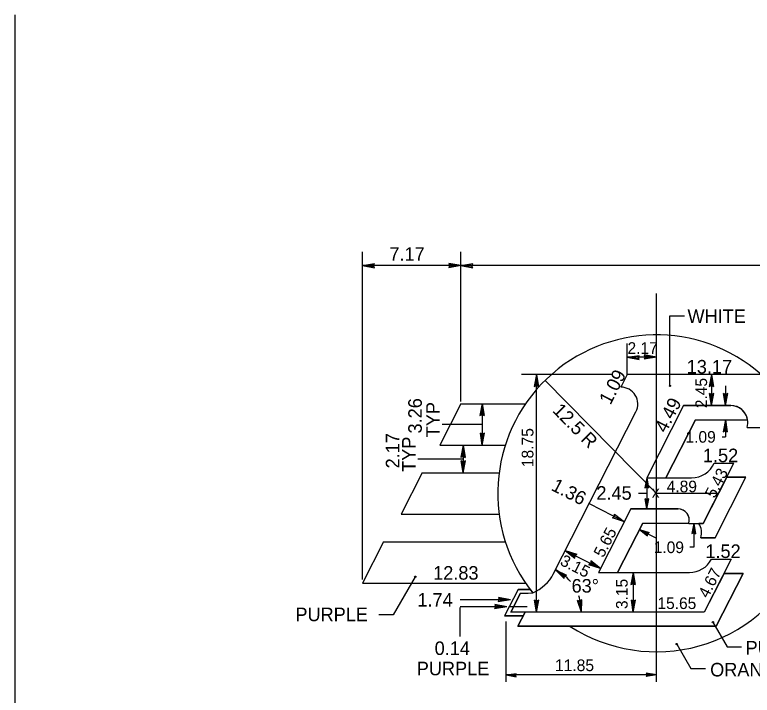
# Model space of a CAD drawing. Extents: x 10268197 to 10268826, y 2141503 to 2142677.
# Drawn here: x 10268664.32 to 10268696.97, y 2142401.45 to 2142431.59 of the extents above; entities that cross this region are included whole.
import ezdxf

# ---------------------------------------------------------------- set-up
doc = ezdxf.new("R2010")
doc.units = 0
for name, color, linetype in [('Default', 7, 'Continuous'), ('NonPlottingEle_dp', 7, 'Continuous'), ('TextMisc', 7, 'Continuous')]:
    doc.layers.add(name, color=color, linetype=linetype)

msp = doc.modelspace()

# ---------------------------------------------------------------- linework, layer by layer
at = {"layer": 'Default'}
for p, q in [((10268679.71, 2142406.582), (10268679.71, 2142421.09)), ((10268684.065, 2142415.347), (10268684.064, 2142421.09)), ((10268679.71, 2142420.48), (10268680.243, 2142420.574)), ((10268679.71, 2142420.48), (10268680.221, 2142420.524)), ((10268684.064, 2142420.48), (10268679.71, 2142420.48)), ((10268679.71, 2142420.48), (10268680.243, 2142420.386)), ((10268679.71, 2142420.48), (10268680.222, 2142420.435)), ((10268680.202, 2142420.48), (10268680.243, 2142420.574)), ((10268680.243, 2142420.386), (10268680.202, 2142420.48)), ((10268684.064, 2142420.48), (10268683.531, 2142420.574)), ((10268683.531, 2142420.574), (10268683.572, 2142420.48)), ((10268684.064, 2142420.48), (10268683.531, 2142420.386)), ((10268683.572, 2142420.48), (10268683.531, 2142420.386)), ((10268684.064, 2142420.48), (10268683.553, 2142420.524)), ((10268684.064, 2142420.48), (10268683.553, 2142420.435)), ((10268684.064, 2142420.48), (10268684.599, 2142420.565)), ((10268684.064, 2142420.48), (10268684.576, 2142420.516)), ((10268724.378, 2142420.48), (10268684.064, 2142420.48)), ((10268684.064, 2142420.48), (10268684.595, 2142420.377)), ((10268684.064, 2142420.48), (10268684.575, 2142420.426)), ((10268684.556, 2142420.471), (10268684.599, 2142420.565)), ((10268684.595, 2142420.377), (10268684.556, 2142420.471)), ((10268692.721, 2142410.391), (10268692.721, 2142419.238)), ((10268693.322, 2142418.257), (10268693.965, 2142418.258)), ((10268693.322, 2142415.153), (10268693.322, 2142418.257)), ((10268691.433, 2142415.653), (10268691.433, 2142417.027)), ((10268692.721, 2142416.417), (10268692.189, 2142416.52)), ((10268692.189, 2142416.52), (10268692.228, 2142416.425)), ((10268691.433, 2142416.417), (10268691.967, 2142416.501)), ((10268691.433, 2142416.417), (10268691.945, 2142416.453)), ((10268692.721, 2142416.417), (10268691.433, 2142416.417)), ((10268691.433, 2142416.417), (10268691.964, 2142416.314)), ((10268691.433, 2142416.417), (10268691.943, 2142416.363)), ((10268691.925, 2142416.408), (10268691.967, 2142416.501)), ((10268691.964, 2142416.314), (10268691.925, 2142416.408)), ((10268692.228, 2142416.425), (10268692.186, 2142416.332)), ((10268692.721, 2142416.417), (10268692.186, 2142416.332)), ((10268692.721, 2142416.417), (10268692.209, 2142416.381)), ((10268692.721, 2142416.417), (10268692.21, 2142416.47)), ((10268690.715, 2142415.653), (10268686.746, 2142415.654)), ((10268687.415, 2142415.653), (10268687.312, 2142415.122)), ((10268687.415, 2142415.653), (10268687.361, 2142415.142)), ((10268687.415, 2142405.129), (10268687.415, 2142415.653)), ((10268687.415, 2142415.653), (10268687.5, 2142415.119)), ((10268687.415, 2142415.653), (10268687.451, 2142415.141)), ((10268691.433, 2142415.653), (10268691.148, 2142415.096)), ((10268698.825, 2142415.653), (10268691.433, 2142415.653)), ((10268695.162, 2142415.653), (10268695.059, 2142415.122)), ((10268695.162, 2142415.653), (10268695.108, 2142415.142)), ((10268695.162, 2142415.653), (10268695.162, 2142414.275)), ((10268695.162, 2142415.653), (10268695.247, 2142415.119)), ((10268695.162, 2142415.653), (10268695.198, 2142415.141)), ((10268684.065, 2142414.457), (10268684.065, 2142415.347)), ((10268692.721, 2142410.391), (10268687.797, 2142415.39)), ((10268687.312, 2142415.122), (10268687.406, 2142415.161)), ((10268687.406, 2142415.161), (10268687.5, 2142415.119)), ((10268695.059, 2142415.122), (10268695.153, 2142415.161)), ((10268695.153, 2142415.161), (10268695.247, 2142415.119)), ((10268695.778, 2142415.155), (10268695.778, 2142414.275)), ((10268695.162, 2142414.275), (10268695.077, 2142414.81)), ((10268695.17, 2142414.768), (10268695.077, 2142414.81)), ((10268695.162, 2142414.275), (10268695.126, 2142414.787)), ((10268695.162, 2142414.275), (10268695.265, 2142414.807)), ((10268695.162, 2142414.275), (10268695.215, 2142414.786)), ((10268695.265, 2142414.807), (10268695.17, 2142414.768)), ((10268695.778, 2142414.275), (10268695.693, 2142414.81)), ((10268695.787, 2142414.767), (10268695.693, 2142414.81)), ((10268695.778, 2142414.275), (10268695.742, 2142414.787)), ((10268695.778, 2142414.275), (10268695.881, 2142414.807)), ((10268695.778, 2142414.275), (10268695.832, 2142414.786)), ((10268695.881, 2142414.807), (10268695.787, 2142414.767)), ((10268684.064, 2142414.351), (10268683.132, 2142412.521)), ((10268684.064, 2142414.351), (10268686.928, 2142414.351)), ((10268685.016, 2142414.374), (10268684.913, 2142413.843)), ((10268685.016, 2142414.374), (10268684.962, 2142413.864)), ((10268685.016, 2142414.374), (10268685.016, 2142412.521)), ((10268685.016, 2142414.374), (10268685.101, 2142413.84)), ((10268685.016, 2142414.374), (10268685.052, 2142413.862)), ((10268693.927, 2142414.275), (10268692.3, 2142411.08)), ((10268693.927, 2142414.275), (10268692.3, 2142411.08)), ((10268693.927, 2142414.275), (10268696.018, 2142414.275)), ((10268696.018, 2142414.275), (10268693.927, 2142414.275)), ((10268688.152, 2142406.806), (10268691.819, 2142414.003)), ((10268684.913, 2142413.843), (10268685.007, 2142413.882)), ((10268685.007, 2142413.882), (10268685.101, 2142413.84)), ((10268694.451, 2142413.649), (10268693.142, 2142411.08)), ((10268693.142, 2142411.08), (10268694.451, 2142413.649)), ((10268694.451, 2142413.649), (10268696.76, 2142413.649)), ((10268694.451, 2142413.649), (10268696.76, 2142413.649)), ((10268695.778, 2142413.649), (10268695.675, 2142413.118)), ((10268695.778, 2142413.649), (10268695.725, 2142413.138)), ((10268695.778, 2142413.649), (10268695.778, 2142412.898)), ((10268695.778, 2142413.649), (10268695.863, 2142413.114)), ((10268695.778, 2142413.649), (10268695.814, 2142413.137)), ((10268685.016, 2142413.448), (10268683.241, 2142413.448)), ((10268696.739, 2142413.309), (10268697.631, 2142413.31)), ((10268685.016, 2142412.521), (10268684.932, 2142413.055)), ((10268685.025, 2142413.013), (10268684.932, 2142413.055)), ((10268685.016, 2142412.521), (10268684.98, 2142413.033)), ((10268685.016, 2142412.521), (10268685.119, 2142413.052)), ((10268685.016, 2142412.521), (10268685.07, 2142413.031)), ((10268685.119, 2142413.052), (10268685.025, 2142413.013)), ((10268695.675, 2142413.118), (10268695.77, 2142413.157)), ((10268695.77, 2142413.157), (10268695.863, 2142413.114)), ((10268695.628, 2142412.898), (10268695.778, 2142412.898)), ((10268683.132, 2142412.521), (10268686.035, 2142412.521)), ((10268684.169, 2142412.521), (10268684.066, 2142411.989)), ((10268684.169, 2142412.521), (10268684.115, 2142412.01)), ((10268684.169, 2142412.521), (10268684.169, 2142411.3)), ((10268684.169, 2142412.521), (10268684.254, 2142411.986)), ((10268684.169, 2142412.521), (10268684.205, 2142412.009)), ((10268684.066, 2142411.989), (10268684.16, 2142412.029)), ((10268684.16, 2142412.029), (10268684.254, 2142411.986)), ((10268684.169, 2142411.911), (10268682.166, 2142411.911)), ((10268684.169, 2142411.3), (10268684.084, 2142411.835)), ((10268684.177, 2142411.792), (10268684.084, 2142411.835)), ((10268684.169, 2142411.3), (10268684.133, 2142411.812)), ((10268684.169, 2142411.3), (10268684.272, 2142411.832)), ((10268684.169, 2142411.3), (10268684.222, 2142411.811)), ((10268684.272, 2142411.832), (10268684.177, 2142411.792)), ((10268694.793, 2142409.051), (10268696.158, 2142411.731)), ((10268695.28, 2142411.731), (10268696.158, 2142411.731)), ((10268682.354, 2142411.3), (10268681.42, 2142409.47)), ((10268682.354, 2142411.3), (10268685.763, 2142411.3)), ((10268692.3, 2142411.08), (10268692.214, 2142410.637)), ((10268692.3, 2142411.08), (10268692.255, 2142410.654)), ((10268692.3, 2142411.08), (10268694.281, 2142411.08)), ((10268692.3, 2142411.08), (10268693.142, 2142411.08)), ((10268692.3, 2142411.08), (10268692.3, 2142409.702)), ((10268692.3, 2142411.08), (10268692.371, 2142410.634)), ((10268692.3, 2142411.08), (10268692.33, 2142410.653)), ((10268695.839, 2142411.104), (10268694.793, 2142409.051)), ((10268695.318, 2142408.425), (10268696.683, 2142411.105)), ((10268695.318, 2142408.425), (10268696.683, 2142411.105)), ((10268695.839, 2142411.104), (10268696.683, 2142411.105)), ((10268696.683, 2142411.105), (10268695.839, 2142411.104)), ((10268692.214, 2142410.637), (10268692.293, 2142410.669)), ((10268692.293, 2142410.669), (10268692.371, 2142410.634)), ((10268692.3, 2142410.391), (10268691.936, 2142410.391)), ((10268692.721, 2142402.042), (10268692.721, 2142410.391)), ((10268695.476, 2142410.391), (10268692.721, 2142410.391)), ((10268692.3, 2142409.702), (10268692.229, 2142410.148)), ((10268692.307, 2142410.113), (10268692.229, 2142410.148)), ((10268692.3, 2142409.702), (10268692.27, 2142410.129)), ((10268692.3, 2142409.702), (10268692.386, 2142410.145)), ((10268692.3, 2142409.702), (10268692.344, 2142410.128)), ((10268692.386, 2142410.145), (10268692.307, 2142410.113)), ((10268691.308, 2142409.134), (10268689.766, 2142409.92)), ((10268691.597, 2142409.702), (10268690.161, 2142406.883)), ((10268691.597, 2142409.702), (10268690.161, 2142406.883)), ((10268691.597, 2142409.702), (10268693.681, 2142409.702)), ((10268693.681, 2142409.702), (10268691.597, 2142409.702)), ((10268681.42, 2142409.47), (10268685.764, 2142409.47)), ((10268692.121, 2142409.076), (10268691.004, 2142406.883)), ((10268691.004, 2142406.883), (10268692.121, 2142409.076)), ((10268692.121, 2142409.076), (10268694.166, 2142409.076)), ((10268692.121, 2142409.076), (10268694.166, 2142409.076)), ((10268694.159, 2142409.051), (10268694.793, 2142409.051)), ((10268694.377, 2142409.051), (10268694.291, 2142408.608)), ((10268694.377, 2142409.051), (10268694.332, 2142408.625)), ((10268694.377, 2142409.051), (10268694.377, 2142408.003)), ((10268694.377, 2142409.051), (10268694.448, 2142408.605)), ((10268694.377, 2142409.051), (10268694.407, 2142408.624)), ((10268694.793, 2142409.051), (10268694.599, 2142409.052)), ((10268691.978, 2142408.793), (10268692.728, 2142408.411)), ((10268691.978, 2142408.793), (10268692.407, 2142408.654)), ((10268691.978, 2142408.793), (10268692.334, 2142408.516)), ((10268691.978, 2142408.793), (10268692.337, 2142408.56)), ((10268691.978, 2142408.793), (10268692.372, 2142408.626)), ((10268692.334, 2142408.516), (10268692.341, 2142408.601)), ((10268692.341, 2142408.601), (10268692.407, 2142408.654)), ((10268694.291, 2142408.608), (10268694.37, 2142408.641)), ((10268694.37, 2142408.641), (10268694.448, 2142408.605)), ((10268695.318, 2142408.425), (10268694.691, 2142408.425)), ((10268694.691, 2142408.425), (10268695.318, 2142408.425)), ((10268680.644, 2142408.25), (10268679.71, 2142406.419)), ((10268680.644, 2142408.25), (10268686.039, 2142408.25)), ((10268688.69, 2142407.861), (10268690.254, 2142407.064)), ((10268688.69, 2142407.861), (10268689.205, 2142407.694)), ((10268688.69, 2142407.861), (10268689.116, 2142407.528)), ((10268688.69, 2142407.861), (10268689.121, 2142407.582)), ((10268688.69, 2142407.861), (10268689.162, 2142407.66)), ((10268694.377, 2142408.003), (10268694.202, 2142408.003)), ((10268689.116, 2142407.528), (10268689.125, 2142407.63)), ((10268689.125, 2142407.63), (10268689.205, 2142407.694)), ((10268689.827, 2142407.397), (10268689.819, 2142407.295)), ((10268690.254, 2142407.064), (10268689.827, 2142407.397)), ((10268696.036, 2142407.473), (10268694.841, 2142405.129)), ((10268695.158, 2142407.473), (10268696.036, 2142407.473)), ((10268689.819, 2142407.295), (10268689.739, 2142407.231)), ((10268690.254, 2142407.064), (10268689.739, 2142407.231)), ((10268690.254, 2142407.064), (10268689.781, 2142407.265)), ((10268690.254, 2142407.064), (10268689.823, 2142407.344)), ((10268688.26, 2142407.011), (10268688.747, 2142406.775)), ((10268688.26, 2142407.011), (10268688.637, 2142406.623)), ((10268688.26, 2142407.011), (10268688.649, 2142406.675)), ((10268688.26, 2142407.011), (10268688.701, 2142406.748)), ((10268688.637, 2142406.623), (10268688.659, 2142406.723)), ((10268688.659, 2142406.723), (10268688.747, 2142406.775)), ((10268690.161, 2142406.883), (10268694.186, 2142406.883)), ((10268690.161, 2142406.883), (10268691.004, 2142406.883)), ((10268691.702, 2142406.883), (10268691.599, 2142406.351)), ((10268691.702, 2142406.883), (10268691.648, 2142406.372)), ((10268691.702, 2142406.883), (10268691.702, 2142405.129)), ((10268691.702, 2142406.883), (10268691.787, 2142406.348)), ((10268691.702, 2142406.883), (10268691.738, 2142406.371)), ((10268695.717, 2142406.846), (10268694.841, 2142405.129)), ((10268696.56, 2142406.846), (10268695.365, 2142404.502)), ((10268695.365, 2142404.502), (10268696.56, 2142406.846)), ((10268695.717, 2142406.846), (10268696.56, 2142406.846)), ((10268696.56, 2142406.846), (10268695.717, 2142406.846)), ((10268679.71, 2142406.419), (10268686.936, 2142406.419)), ((10268682.047, 2142406.698), (10268681.077, 2142405.018)), ((10268691.599, 2142406.351), (10268691.693, 2142406.39)), ((10268691.693, 2142406.39), (10268691.787, 2142406.348)), ((10268686.6, 2142406.138), (10268686.001, 2142404.961)), ((10268686.6, 2142406.138), (10268687.146, 2142406.138)), ((10268686.261, 2142405.678), (10268685.73, 2142405.781)), ((10268685.73, 2142405.781), (10268685.769, 2142405.686)), ((10268686.702, 2142405.971), (10268686.274, 2142405.129)), ((10268686.702, 2142405.971), (10268687.053, 2142405.971)), ((10268687.053, 2142405.971), (10268687.258, 2142405.987)), ((10268686.261, 2142405.678), (10268684.035, 2142405.678)), ((10268686.098, 2142405.359), (10268685.567, 2142405.462)), ((10268685.567, 2142405.462), (10268685.606, 2142405.367)), ((10268686.098, 2142405.359), (10268685.588, 2142405.412)), ((10268685.769, 2142405.686), (10268685.726, 2142405.593)), ((10268686.261, 2142405.678), (10268685.726, 2142405.593)), ((10268686.261, 2142405.678), (10268685.749, 2142405.642)), ((10268686.261, 2142405.678), (10268685.75, 2142405.731)), ((10268687.415, 2142405.129), (10268687.33, 2142405.663)), ((10268687.423, 2142405.621), (10268687.33, 2142405.663)), ((10268687.415, 2142405.129), (10268687.379, 2142405.64)), ((10268687.415, 2142405.129), (10268687.518, 2142405.66)), ((10268687.415, 2142405.129), (10268687.468, 2142405.639)), ((10268687.518, 2142405.66), (10268687.423, 2142405.621)), ((10268689.41, 2142405.132), (10268689.234, 2142405.644)), ((10268689.333, 2142405.618), (10268689.234, 2142405.644)), ((10268689.41, 2142405.132), (10268689.286, 2142405.63)), ((10268689.42, 2142405.673), (10268689.333, 2142405.618)), ((10268689.41, 2142405.132), (10268689.374, 2142405.644)), ((10268689.41, 2142405.132), (10268689.42, 2142405.673)), ((10268691.702, 2142405.129), (10268691.617, 2142405.663)), ((10268691.71, 2142405.621), (10268691.617, 2142405.663)), ((10268691.702, 2142405.129), (10268691.666, 2142405.64)), ((10268691.702, 2142405.129), (10268691.805, 2142405.66)), ((10268691.702, 2142405.129), (10268691.755, 2142405.639)), ((10268691.805, 2142405.66), (10268691.71, 2142405.621)), ((10268686.098, 2142405.359), (10268684.035, 2142405.359)), ((10268684.035, 2142404.056), (10268684.035, 2142405.339)), ((10268685.606, 2142405.367), (10268685.564, 2142405.274)), ((10268686.098, 2142405.359), (10268685.564, 2142405.274)), ((10268686.098, 2142405.359), (10268685.586, 2142405.323)), ((10268687, 2142405.359), (10268686.187, 2142405.359)), ((10268694.841, 2142405.129), (10268686.274, 2142405.129)), ((10268686.594, 2142404.502), (10268686.913, 2142405.129)), ((10268686.913, 2142405.129), (10268686.594, 2142404.502)), ((10268694.841, 2142405.129), (10268686.913, 2142405.129)), ((10268681.077, 2142405.018), (10268680.434, 2142405.017)), ((10268686.828, 2142404.961), (10268686.001, 2142404.961)), ((10268686.07, 2142402.042), (10268686.07, 2142404.715)), ((10268695.365, 2142404.502), (10268686.594, 2142404.502)), ((10268686.594, 2142404.502), (10268695.365, 2142404.502)), ((10268695.224, 2142404.685), (10268695.853, 2142403.595)), ((10268693.624, 2142403.717), (10268694.253, 2142402.627)), ((10268695.853, 2142403.595), (10268696.496, 2142403.595)), ((10268694.253, 2142402.627), (10268694.896, 2142402.627)), ((10268686.07, 2142402.348), (10268686.516, 2142402.419)), ((10268686.07, 2142402.348), (10268686.497, 2142402.378)), ((10268692.721, 2142402.348), (10268686.07, 2142402.348)), ((10268686.07, 2142402.348), (10268686.513, 2142402.262)), ((10268686.07, 2142402.348), (10268686.496, 2142402.303)), ((10268686.481, 2142402.341), (10268686.516, 2142402.419)), ((10268686.513, 2142402.262), (10268686.481, 2142402.341)), ((10268692.31, 2142402.355), (10268692.275, 2142402.278)), ((10268692.721, 2142402.348), (10268692.275, 2142402.278)), ((10268692.721, 2142402.348), (10268692.277, 2142402.434)), ((10268692.277, 2142402.434), (10268692.31, 2142402.355)), ((10268692.721, 2142402.348), (10268692.293, 2142402.319)), ((10268692.721, 2142402.348), (10268692.294, 2142402.393))]:
    msp.add_line(p, q, dxfattribs=at)
for points in [[(10268691.308, 2142409.134), (10268690.784, 2142409.305), (10268690.863, 2142409.37), (10268690.873, 2142409.473)], [(10268687.146, 2142406.138), (10268686.6, 2142406.138), (10268686.001, 2142404.961), (10268686.828, 2142404.961), (10268686.913, 2142405.129), (10268686.274, 2142405.129), (10268686.702, 2142405.971), (10268687.053, 2142405.971), (10268687.258, 2142405.987)]]:
    msp.add_lwpolyline(points, close=True, dxfattribs=at)
for centre in [(10268693.322, 2142415.153), (10268682.047, 2142406.699), (10268695.224, 2142404.685), (10268693.624, 2142403.717)]:
    msp.add_circle(centre, 0.0305, dxfattribs=at)
for centre, radius, start, end in [((10268692.721, 2142410.391), 7.017, 48.5904, 218.8792), ((10268691.15, 2142414.344), 0.752, 333.0033, 90.1042), ((10268696.019, 2142413.524), 0.752, 343.4611, 90), ((10268696.019, 2142413.524), 0.752, 9.5941, 90), ((10268694.282, 2142412.17), 1.09, 270, 336.2493), ((10268693.68, 2142409.201), 0.501, 342.6625, 90), ((10268693.68, 2142409.201), 0.501, 345.5225, 90), ((10268693.971, 2142408.639), 0.752, 343.4611, 33.2756), ((10268693.971, 2142408.639), 0.752, 343.4611, 33.2756), ((10268694.186, 2142407.979), 1.096, 270, 332.5096), ((10268692.721, 2142410.391), 7.017, 237.0648, 334.1734), ((10268686.538, 2142407.67), 1.831, 293.1567, 333.0112), ((10268687.298, 2142405.129), 2.113, 40.0298, 62.999), ((10268687.298, 2142405.129), 2.113, 0, 19.9667)]:
    msp.add_arc(centre, radius, start, end, dxfattribs=at)
at = {"layer": 'NonPlottingEle_dp'}
msp.add_line((10268664.322, 2142431.588), (10268664.322, 2142335.588), dxfattribs=at)

# ---------------------------------------------------------------- texts
at = {"layer": 'Default'}
for s, height, p in [('7.17', 0.5999, (10268680.906, 2142420.692)), ('WHITE', 0.5999, (10268694.1, 2142417.94)), ('2.17', 0.5142, (10268691.446, 2142416.57)), ('13.17', 0.5999, (10268694.066, 2142415.699)), ('1.09', 0.5142, (10268694.012, 2142412.635)), ('1.52', 0.5999, (10268694.782, 2142411.771)), ('4.89', 0.5142, (10268693.18, 2142410.439)), ('x', 0.517, (10268692.517, 2142410.196)), ('1.09', 0.5142, (10268692.605, 2142407.746)), ('1.52', 0.5999, (10268694.892, 2142407.528)), ('12.83', 0.5999, (10268682.842, 2142406.569)), ('63°', 0.5999, (10268688.969, 2142405.997)), ('1.74', 0.5999, (10268682.146, 2142405.376)), ('15.65', 0.5142, (10268692.769, 2142405.269)), ('PURPLE', 0.5999, (10268676.745, 2142404.73)), ('0.14', 0.5999, (10268682.908, 2142403.233)), ('PURPLE', 0.5999, (10268696.671, 2142403.254)), ('PURPLE', 0.5999, (10268682.117, 2142402.333)), ('11.85', 0.5174, (10268688.233, 2142402.518)), ('ORANGE', 0.5999, (10268695.103, 2142402.283))]:
    msp.add_text(s, height=height, dxfattribs=at).set_placement(p)
for s, height, rotation, p in [('1.09', 0.5999, 62.9854, (10268690.692, 2142414.276)), ('2.45', 0.5142, 90, (10268694.966, 2142414.163)), ('3.26', 0.5999, 90, (10268682.34, 2142413.044)), ('4.49', 0.5999, 63.012, (10268693.149, 2142413.032)), ('TYP', 0.5999, 90, (10268683.133, 2142412.875)), ('12.5 R', 0.5999, 314.5624, (10268688.09, 2142414.025)), ('18.75', 0.5174, 90, (10268687.281, 2142411.55)), ('2.17', 0.5999, 90, (10268681.347, 2142411.497)), ('TYP', 0.5999, 90, (10268682.065, 2142411.343)), ('5.43', 0.5142, 63.0087, (10268695.305, 2142410.142)), ('1.36', 0.5999, 333.0041, (10268688.025, 2142410.551)), ('2.45', 0.5999, 360, (10268690.067, 2142410.109)), ('5.65', 0.5142, 63.0001, (10268690.375, 2142407.513)), ('3.15', 0.5142, 333.0028, (10268688.42, 2142407.243)), ('4.67', 0.5142, 62.9952, (10268695.008, 2142405.718))]:
    msp.add_text(s, height=height, rotation=rotation, dxfattribs=at).set_placement(p)
at = {"layer": 'TextMisc'}
msp.add_text('3.15', height=0.5142, rotation=90, dxfattribs=at).set_placement((10268691.451, 2142405.268))

doc.saveas('drawing.dxf')
